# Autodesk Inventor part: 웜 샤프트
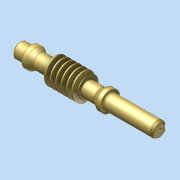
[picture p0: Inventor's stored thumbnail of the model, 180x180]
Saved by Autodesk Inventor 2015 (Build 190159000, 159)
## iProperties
Created: 2026-02
Part Number: 웜 샤프트
Material: 일반
Document SubType Name: Modeling
Designer: Administrator
Density: 1 g/cm^3
Appearance: 기본값
Author: Administrator
Author: jhkim
Creation Date: 2026-01-30
Sending System: Autodesk Inventor 2026
Preprocessor: ST-DEVELOPER v20.1
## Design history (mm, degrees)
node "웜 샤프트1"
node "솔리드1"
node "기준1"
